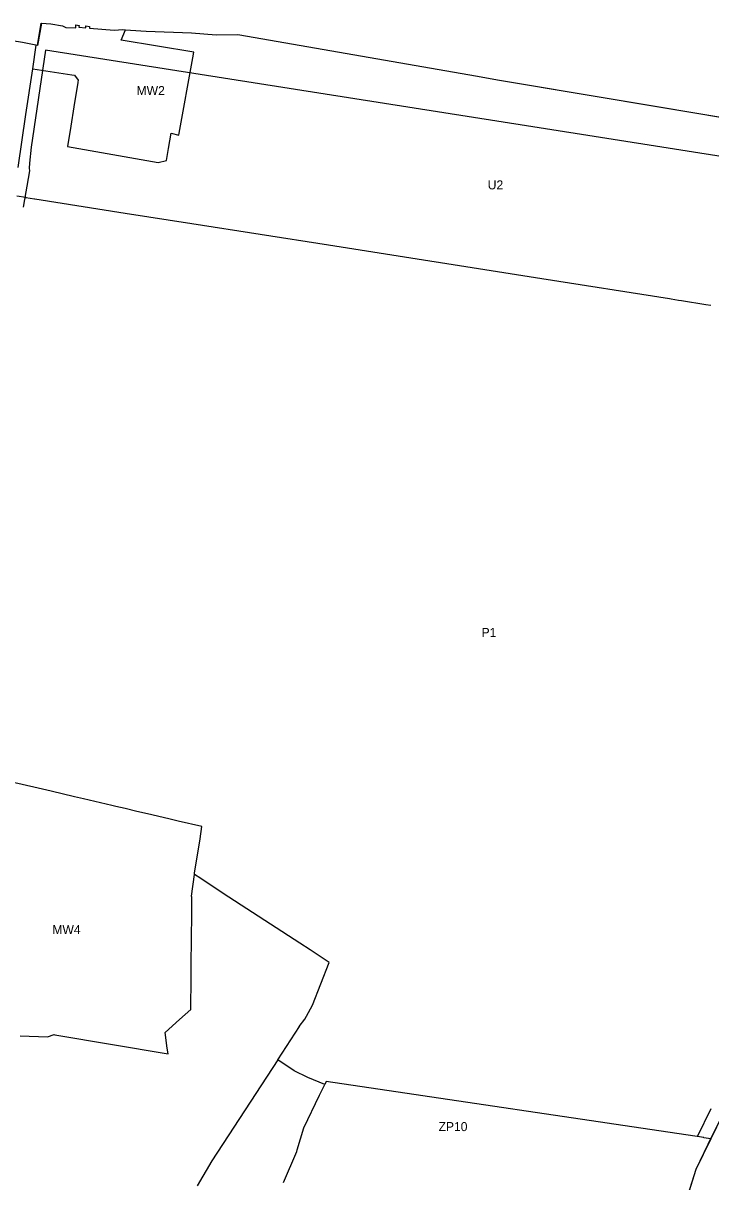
# Model space of a CAD drawing. Extents: x 7428103 to 7431580, y 5545880 to 5549002.
# Drawn here: x 7429796 to 7430217, y 5548288 to 5548999 of the extents above; entities that cross this region are included whole.
import ezdxf

# ---------------------------------------------------------------- set-up
doc = ezdxf.new("R2010")
doc.units = 0
for name, color, linetype in [('CZ_L_granica obszaru objętego planem', 7, 'Continuous'), ('CZ_L_linie rozgraniczające tereny o różnym przeznaczeniu oraz różnych warunkach ich zabudowy i zagospodarowania', 7, 'Continuous'), ('CZ_L_maksymalne nieprzekraczalne linie zabudowy', 7, 'Continuous'), ('CZ_L_opisy_linie rozgraniczające tereny o różnym przeznaczeniu oraz różnych warunkach ich zabudowy i zagospodarowania', 7, 'Continuous'), ('Łąki_Nowohuckie', 7, 'Continuous')]:
    doc.layers.add(name, color=color, linetype=linetype)

msp = doc.modelspace()

# ---------------------------------------------------------------- linework, layer by layer
at = {"layer": 'CZ_L_granica obszaru objętego planem'}
for p, q in [((7429804.32, 5548985.03), (7429806.69, 5548998.57)), ((7429806.69, 5548998.57), (7429812.45, 5548998.22)), ((7429812.45, 5548998.22), (7429819.6, 5548997.01)), ((7429819.6, 5548997.01), (7429821.8, 5548995.94)), ((7429821.8, 5548995.94), (7429827.86, 5548995.69)), ((7429827.86, 5548995.69), (7429827.79, 5548997.49)), ((7429827.79, 5548997.49), (7429829.8, 5548997.22)), ((7429829.8, 5548997.22), (7429829.7, 5548996.11)), ((7429829.7, 5548996.11), (7429834.07, 5548995.74)), ((7429834.07, 5548995.74), (7429834.02, 5548996.94)), ((7429834.02, 5548996.94), (7429836.23, 5548996.58)), ((7429836.23, 5548996.58), (7429836.28, 5548995.53)), ((7429836.28, 5548995.53), (7429851.44, 5548994.29)), ((7429851.44, 5548994.29), (7429856.63, 5548994.61)), ((7429856.63, 5548994.61), (7429858.18, 5548994.5)), ((7429858.18, 5548994.5), (7429870.98, 5548993.64)), ((7429870.98, 5548993.64), (7429898.69, 5548992.61)), ((7429795.21, 5548986.84), (7429804.32, 5548985.03)), ((7429898.69, 5548992.61), (7429913.85, 5548991.37)), ((7429913.85, 5548991.37), (7429927.18, 5548991.72)), ((7429927.18, 5548991.72), (7430074.1, 5548966)), ((7430074.1, 5548966), (7430086.49, 5548963.83)), ((7430086.49, 5548963.83), (7430240.28, 5548938.14))]:
    msp.add_line(p, q, dxfattribs=at)
at = {"layer": 'CZ_L_linie rozgraniczające tereny o różnym przeznaczeniu oraz różnych warunkach ich zabudowy i zagospodarowania'}
for p, q in [((7429855.74, 5548988.16), (7429858.27, 5548994.49)), ((7429900.17, 5548980.72), (7429855.74, 5548988.16)), ((7429801.42, 5548970.6), (7429803.56, 5548985.07)), ((7429899.56, 5548977.33), (7429900.17, 5548980.72)), ((7429891.2, 5548931.1), (7429899.56, 5548977.33)), ((7429797.29, 5548942.62), (7429801.42, 5548970.6)), ((7429801.42, 5548970.6), (7429825.5, 5548966.85)), ((7429825.5, 5548966.85), (7429827.07, 5548966.62)), ((7429827.07, 5548966.62), (7429829.25, 5548963.61)), ((7429829.05, 5548962.19), (7429826.54, 5548947.26)), ((7429829.09, 5548962.41), (7429829.05, 5548962.19)), ((7429829.25, 5548963.61), (7429829.08, 5548962.42)), ((7429829.08, 5548962.42), (7429829.09, 5548962.41)), ((7429826.54, 5548947.26), (7429824.8, 5548935.51)), ((7429792.42, 5548910.02), (7429797.29, 5548942.62)), ((7429824.8, 5548935.51), (7429822.76, 5548922.97)), ((7429884.68, 5548921.73), (7429886.35, 5548931.19)), ((7429886.35, 5548931.19), (7429890.99, 5548929.99)), ((7429890.99, 5548929.99), (7429891.2, 5548931.1)), ((7429822.76, 5548922.97), (7429878.29, 5548913.09)), ((7429883.39, 5548914.41), (7429884.68, 5548921.73)), ((7429878.29, 5548913.09), (7429883.39, 5548914.41)), ((7429791.76, 5548892.74), (7429797.15, 5548891.83)), ((7429797.15, 5548891.83), (7429797.13, 5548891.62)), ((7429797.13, 5548891.62), (7429802.52, 5548890.79)), ((7429802.52, 5548890.79), (7429802.64, 5548890.8)), ((7429802.64, 5548890.8), (7429858.01, 5548882.14)), ((7429858.01, 5548882.14), (7429898.98, 5548875.73)), ((7429898.98, 5548875.73), (7429982.71, 5548862.61)), ((7429982.71, 5548862.61), (7430113.67, 5548842.1)), ((7430113.67, 5548842.1), (7430113.67, 5548842.1)), ((7430113.67, 5548842.1), (7430113.69, 5548842.1)), ((7430113.69, 5548842.1), (7430191.88, 5548829.65)), ((7430191.88, 5548829.65), (7430193.01, 5548829.47)), ((7430193.01, 5548829.47), (7430197.5, 5548828.75)), ((7430197.5, 5548828.75), (7430199.32, 5548828.46)), ((7430199.32, 5548828.46), (7430214.13, 5548826.1)), ((7430214.13, 5548826.1), (7430217.3, 5548825.6)), ((7429802.09, 5548530.01), (7429790.45, 5548532.71)), ((7429812.74, 5548527.52), (7429802.09, 5548530.01)), ((7429827.01, 5548524.19), (7429812.74, 5548527.52)), ((7429832.59, 5548522.88), (7429827.01, 5548524.19)), ((7429849.85, 5548518.84), (7429832.59, 5548522.88)), ((7429852.28, 5548518.28), (7429849.85, 5548518.84)), ((7429858.08, 5548516.92), (7429852.28, 5548518.28)), ((7429865.29, 5548515.24), (7429858.08, 5548516.92)), ((7429871.79, 5548513.72), (7429865.29, 5548515.24)), ((7429884.79, 5548510.68), (7429871.79, 5548513.72)), ((7429890.68, 5548509.31), (7429884.79, 5548510.68)), ((7429905.2, 5548505.92), (7429890.68, 5548509.31)), ((7429904, 5548498.36), (7429905.2, 5548505.92)), ((7429900.68, 5548477.42), (7429904, 5548498.36)), ((7429898.74, 5548463.27), (7429900.56, 5548476.55)), ((7429900.56, 5548476.55), (7429900.68, 5548477.42)), ((7429904.49, 5548473.97), (7429900.56, 5548476.55)), ((7429918.28, 5548464.92), (7429904.49, 5548473.97)), ((7429898.7, 5548462.98), (7429898.74, 5548463.27)), ((7429899.02, 5548462.88), (7429898.7, 5548462.98)), ((7429898.94, 5548455.18), (7429899.02, 5548462.88)), ((7429918.28, 5548464.91), (7429918.28, 5548464.92)), ((7429965.25, 5548434.31), (7429918.28, 5548464.91)), ((7429898.75, 5548436.19), (7429898.92, 5548453.02)), ((7429898.92, 5548453.02), (7429898.94, 5548455.18)), ((7429898.6, 5548421.9), (7429898.75, 5548436.19)), ((7429971.53, 5548430.21), (7429965.25, 5548434.31)), ((7429983.18, 5548422.62), (7429971.53, 5548430.21)), ((7429898.52, 5548413.33), (7429898.6, 5548421.9)), ((7429973, 5548396.44), (7429983.18, 5548422.62)), ((7429898.32, 5548393.62), (7429898.52, 5548413.33)), ((7429969.27, 5548389.59), (7429973, 5548396.44)), ((7429891.41, 5548387.5), (7429898.32, 5548393.62)), ((7429968.33, 5548387.85), (7429969.27, 5548389.59)), ((7429882.63, 5548379.71), (7429891.41, 5548387.5)), ((7429951.71, 5548362.8), (7429965.07, 5548383.26)), ((7429964.89, 5548383.37), (7429968.33, 5548387.85)), ((7429965.07, 5548383.26), (7429964.89, 5548383.37)), ((7429793.66, 5548377.55), (7429810.39, 5548377.05)), ((7429810.39, 5548377.05), (7429814.57, 5548378.32)), ((7429814.57, 5548378.32), (7429814.53, 5548378.45)), ((7429814.53, 5548378.45), (7429814.92, 5548378.2)), ((7429814.92, 5548378.2), (7429884.42, 5548366.51)), ((7429883.95, 5548369.97), (7429882.63, 5548379.71)), ((7429884.42, 5548366.51), (7429883.95, 5548369.97)), ((7429951.71, 5548362.8), (7429911.31, 5548300.91)), ((7429961.77, 5548356.02), (7429951.71, 5548362.8)), ((7429970.22, 5548351.93), (7429961.77, 5548356.02)), ((7429980.47, 5548347.63), (7429970.22, 5548351.93)), ((7429979.34, 5548345.31), (7429980.47, 5548347.63)), ((7429981.46, 5548349.67), (7429980.47, 5548347.63)), ((7430212.99, 5548315.17), (7429981.46, 5548349.67)), ((7429967.64, 5548321.22), (7429977.33, 5548341.17)), ((7429977.33, 5548341.17), (7429979.34, 5548345.31)), ((7430224.45, 5548329.12), (7430217.23, 5548314.32)), ((7429963.59, 5548307.67), (7429967.64, 5548321.22)), ((7430217.23, 5548314.32), (7430208.15, 5548295.69)), ((7430212.91, 5548315.01), (7430212.99, 5548315.17)), ((7430217.23, 5548314.32), (7430212.91, 5548315.01)), ((7429955.17, 5548287.65), (7429963.28, 5548306.64)), ((7429963.28, 5548306.64), (7429963.59, 5548307.67)), ((7429911.31, 5548300.91), (7429902.3, 5548285.56)), ((7430208.15, 5548295.69), (7430203.82, 5548281.96))]:
    msp.add_line(p, q, dxfattribs=at)
for points in [[(7429806.72, 5548998.57), (7429804.33, 5548984.92), (7429795.22, 5548986.74), (7429788.84, 5548987.84), (7429748.76, 5548994.26), (7429721.53, 5548986.15), (7429715.88, 5548982.47), (7429693.34, 5548968.21), (7429683.95, 5548953.05), (7429672.03, 5548954.18), (7429664.24, 5548947.89), (7429654.93, 5548934.8), (7429647.87, 5548918.39), (7429649, 5548910.4), (7429647.62, 5548901.93)], [(7429806.72, 5548998.57), (7429812.45, 5548998.22), (7429819.6, 5548997.01), (7429821.8, 5548995.94), (7429827.86, 5548995.69), (7429827.79, 5548997.49), (7429829.8, 5548997.22), (7429829.7, 5548996.11), (7429834.07, 5548995.74), (7429834.02, 5548996.94), (7429836.23, 5548996.58), (7429836.28, 5548995.53), (7429851.44, 5548994.29), (7429856.63, 5548994.61), (7429858.18, 5548994.5), (7429858.27, 5548994.49)], [(7429858.27, 5548994.49), (7429870.98, 5548993.64), (7429898.69, 5548992.61), (7429913.85, 5548991.37), (7429927.18, 5548991.72), (7430074.1, 5548966), (7430086.49, 5548963.83), (7430240.28, 5548938.14), (7430239.23, 5548929.76), (7430261.25, 5548926.5), (7430275.34, 5548924.41), (7430311.25, 5548917.71), (7430311.61, 5548919.78), (7430369.8, 5548910.09)]]:
    msp.add_lwpolyline(points, dxfattribs=at)
at = {"layer": 'CZ_L_maksymalne nieprzekraczalne linie zabudowy'}
for points in [[(7430360.94, 5548895.1), (7430108.03, 5548935.09), (7429809.17, 5548981.99), (7429800.45, 5548922.62), (7429799.4, 5548912.72), (7429799.29, 5548909.64), (7429799.45, 5548907.98), (7429795.56, 5548885.78)], [(7430209.1, 5548315.89), (7430217.49, 5548333.07)]]:
    msp.add_lwpolyline(points, dxfattribs=at)
at = {"layer": 'Łąki_Nowohuckie'}
msp.add_lwpolyline([(7430297.2, 5548430.43), (7430238.13, 5548349.75), (7430225.26, 5548330.6), (7430217.87, 5548316.02), (7430208.17, 5548295.59), (7430203.25, 5548280.01)], dxfattribs=at)

# ---------------------------------------------------------------- texts
at = {"layer": 'CZ_L_opisy_linie rozgraniczające tereny o różnym przeznaczeniu oraz różnych warunkach ich zabudowy i zagospodarowania'}
for s, p in [('MW2', (7429865.11, 5548954.47)), ('U2', (7430080.46, 5548896.64)), ('P1', (7430076.67, 5548622.18)), ('MW4', (7429813.47, 5548439.93)), ('ZP10', (7430050.29, 5548319.15))]:
    msp.add_text(s, height=5.549, dxfattribs=at).set_placement(p)

doc.saveas('drawing.dxf')
